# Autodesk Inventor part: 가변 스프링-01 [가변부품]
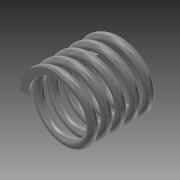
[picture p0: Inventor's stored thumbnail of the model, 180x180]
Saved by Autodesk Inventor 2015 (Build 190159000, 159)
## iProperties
Created: 2015-05
Part Number: 가변 스프링-01 [가변부품]
Material: 강철, 탄소
Document SubType Name: Modeling
Designer: Young-Hwan
Density: 7.85 g/cm^3
Appearance: 반연마
Mass: 18.6943 g
Surface Area: 32.3824 cm^2
Volume: 2.38144 cm^3
Author: Young-Hwan
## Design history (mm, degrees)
sketch "스케치1"
  geometry: L1 (0, 0)-(-11, 0); L2 (-11, 0)-(-11, 25.358); L3 (-11, 25.358)-(0, 25.358); L4 (0, 25.358)-(0, 0); C1 r 1.5 at (-11, 0)
  constraints: 8 end point, 2 parallel, 1 centre point, 1 coincident, 1 horizontal, 1 perpendicular
  dimensions: "d0" = 22 diameter of L2 L4; "d1" = 25.35829 distance between parallel lines of L3 L1 (derived); "d2" = 3 diameter of C1 (derived)
feature "코일1" sketch "스케치1" pitch "d3" = 10; turns "d5" = 5; dims "d4" = 25.35829 (= d1), "d6" = 0, angle "d7" = 90 deg, angle "d8" = 90 deg, "d9" = 0, "d10" = 0
sketch "스케치2"
  geometry: L1 (12.5, 0)-(9.5, 0) reference; 1 further point
  constraints: 1 horizontal alignment
extrude "돌출1" cut sketch "스케치2" stored distance "d11" = 10; taper "d12" = 0 deg
node "작업 평면1"
sketch "스케치3"
  geometry: L1 (-1.5, 0)-(1.5, 0) reference; 1 further point
  constraints: 1 horizontal alignment
extrude "돌출2" cut sketch "스케치3" stored distance "d14" = 10; taper "d15" = 0 deg
node "솔리드1"
node "절단 모서리 투영1"
node "절단 모서리 투영2"
other parameters: "d13" = 90 deg
